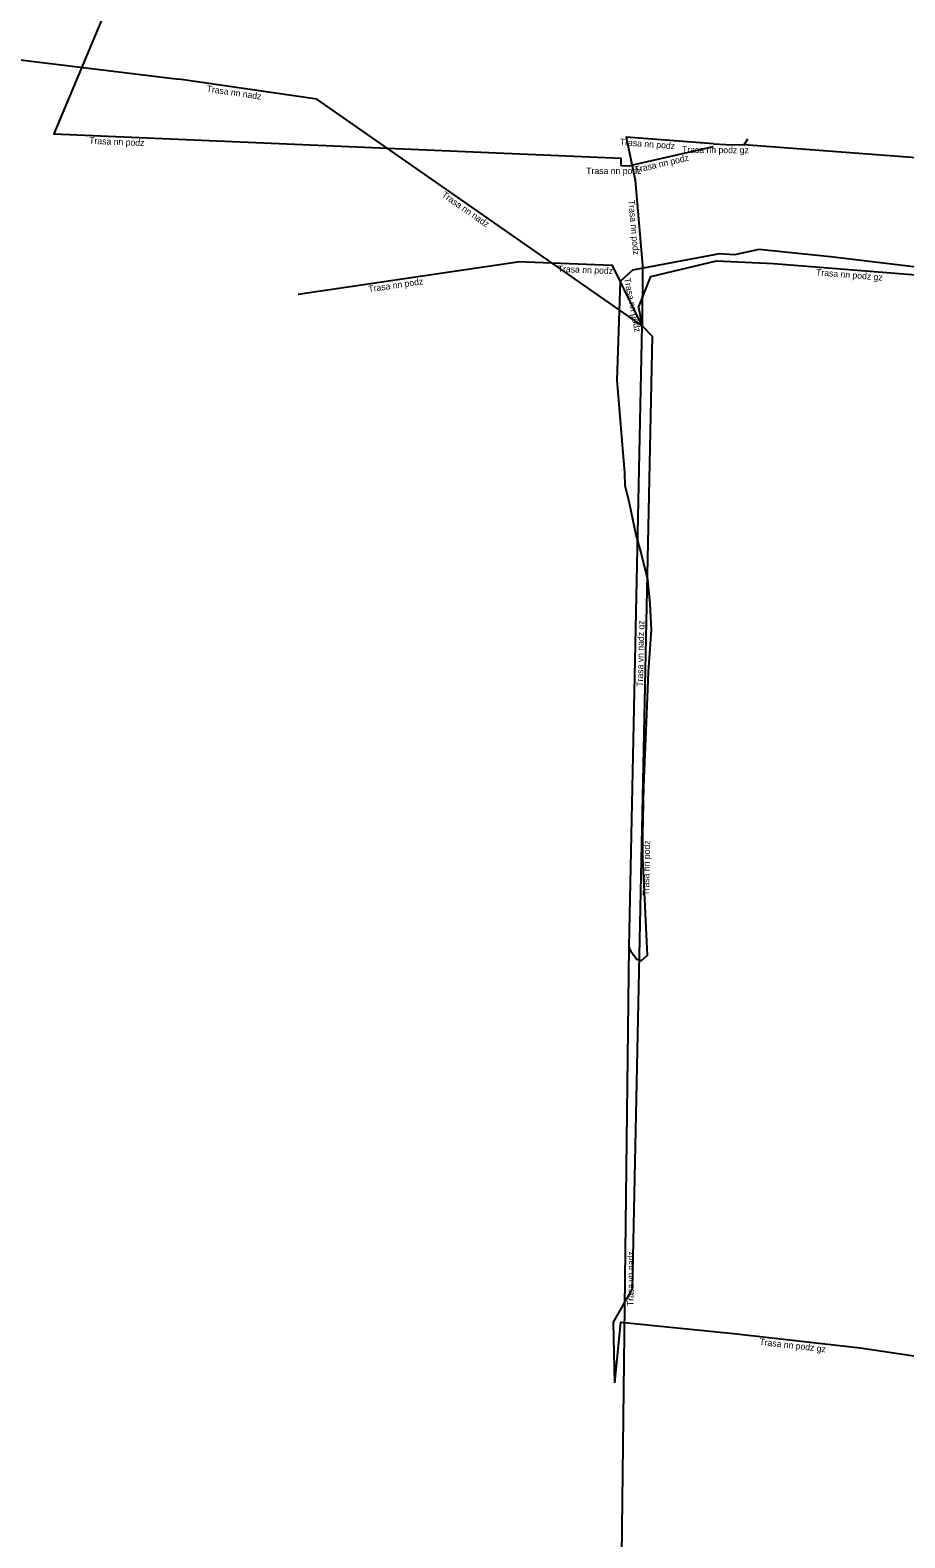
# Model space of a CAD drawing. Extents: x -728120 to -727345, y -1063477 to -1062892.
# Drawn here: x -727740.6 to -727672.9, y -1063348.1 to -1063231.4 of the extents above; entities that cross this region are included whole.
import ezdxf

# ---------------------------------------------------------------- set-up
doc = ezdxf.new("R2010")
doc.units = 0
for name, color, linetype in [('Popiskový text - Ostatní atributy Trasy', 7, 'Continuous'), ('Spojnice NN', 7, 'Continuous'), ('Spojnice VN', 7, 'Continuous')]:
    doc.layers.add(name, color=color, linetype=linetype)

msp = doc.modelspace()

# ---------------------------------------------------------------- linework, layer by layer
at = {"layer": 'Spojnice NN'}
for points in [[(-727726.13, -1063209.26), (-727738.77, -1063239.41), (-727694.89, -1063241.29), (-727694.89, -1063241.87)], [(-727757.87, -1063231.68), (-727729.09, -1063235.19)], [(-727718.43, -1063236.74), (-727729.09, -1063235.19)], [(-727693.25, -1063254.27), (-727718.43, -1063236.74)], [(-727687.71, -1063240.18), (-727694.47, -1063239.67), (-727694.19, -1063241.03)], [(-727687.71, -1063240.18), (-727686.76, -1063240.25), (-727685.36, -1063240.26), (-727685.07, -1063239.79)], [(-727694.19, -1063241.03), (-727693.79, -1063243.01), (-727693.21, -1063249.61), (-727693.25, -1063254.27)], [(-727693.97, -1063241.82), (-727687.72, -1063240.38)], [(-727632.55, -1063244.23), (-727660.27, -1063242.15), (-727673.42, -1063241.16), (-727685.36, -1063240.26)], [(-727694.89, -1063241.87), (-727694.22, -1063241.88), (-727693.97, -1063241.82)], [(-727719.87, -1063251.82), (-727702.88, -1063249.32)], [(-727693.25, -1063254.27), (-727695.53, -1063249.61), (-727702.88, -1063249.32)], [(-727693.53, -1063252.86), (-727692.58, -1063250.46), (-727687.5, -1063249.24), (-727683.09, -1063249.44), (-727670.11, -1063250.49), (-727656.49, -1063252.01)], [(-727693.53, -1063252.86), (-727693.25, -1063254.27)], [(-727695.37, -1063336.1), (-727695.47, -1063331.38), (-727694, -1063328.81), (-727692.45, -1063255.1), (-727693.25, -1063254.27)], [(-727695.37, -1063336.1), (-727694.89, -1063331.39), (-727686.18, -1063332.26), (-727676.37, -1063333.39), (-727661.67, -1063335.57), (-727661.55, -1063334.89)]]:
    msp.add_lwpolyline(points, dxfattribs=at)
at = {"layer": 'Spojnice VN'}
for points in [[(-727667.95, -1063250.23), (-727678.67, -1063248.93), (-727684.22, -1063248.37), (-727686.09, -1063248.79), (-727687.27, -1063248.71), (-727693.98, -1063249.96), (-727694.95, -1063250.83), (-727695.2, -1063258.48), (-727694.61, -1063265.64), (-727694.58, -1063266.6), (-727694.24, -1063267.98), (-727693.73, -1063270.45), (-727693.31, -1063271.93), (-727692.83, -1063273.9), (-727692.64, -1063275.78), (-727692.54, -1063277.78), (-727692.79, -1063281.08), (-727692.95, -1063285.63), (-727693.13, -1063289.9), (-727693.22, -1063293.69), (-727693.21, -1063295.41), (-727692.85, -1063303), (-727693.32, -1063303.42), (-727693.66, -1063303.33), (-727694.07, -1063302.77), (-727694.24, -1063302.34)], [(-727694.24, -1063302.34), (-727693.25, -1063254.27)], [(-727694.83, -1063351.65), (-727694.24, -1063302.34)]]:
    msp.add_lwpolyline(points, dxfattribs=at)

# ---------------------------------------------------------------- texts
at = {"layer": 'Popiskový text - Ostatní atributy Trasy'}
for s, rotation, p in [('Trasa nn nadz', 351.6855, (-727726.97, -1063236.15)), ('Trasa nn podz', 357.5448, (-727736.04, -1063240.18)), ('Trasa nn podz', 355.6523, (-727694.98, -1063240.28)), ('Trasa nn podz gz', 359.5908, (-727690.16, -1063240.88)), ('Trasa nn podz', 359.8933, (-727697.57, -1063242.52)), ('Trasa nn podz', 12.9494, (-727693.76, -1063242.44)), ('Trasa nn nadz', 325.1511, (-727708.8, -1063244.24)), ('Trasa nn podz', 275.0087, (-727694.31, -1063244.55)), ('Trasa nn podz', 357.7645, (-727699.78, -1063250.1)), ('Trasa nn podz gz', 355.3752, (-727679.8, -1063250.36)), ('Trasa nn podz', 8.3656, (-727714.39, -1063251.68)), ('Trasa nn podz', 281.3489, (-727694.65, -1063250.61)), ('Trasa vn nadz gz', 88.8206, (-727693.18, -1063282.21)), ('Trasa nn podz', 88.7957, (-727692.71, -1063298.38)), ('Trasa vn nadz', 89.3203, (-727693.92, -1063330.15)), ('Trasa nn podz gz', 353.4291, (-727684.19, -1063333.14))]:
    msp.add_text(s, height=0.5, rotation=rotation, dxfattribs=at).set_placement(p)

doc.saveas('drawing.dxf')
